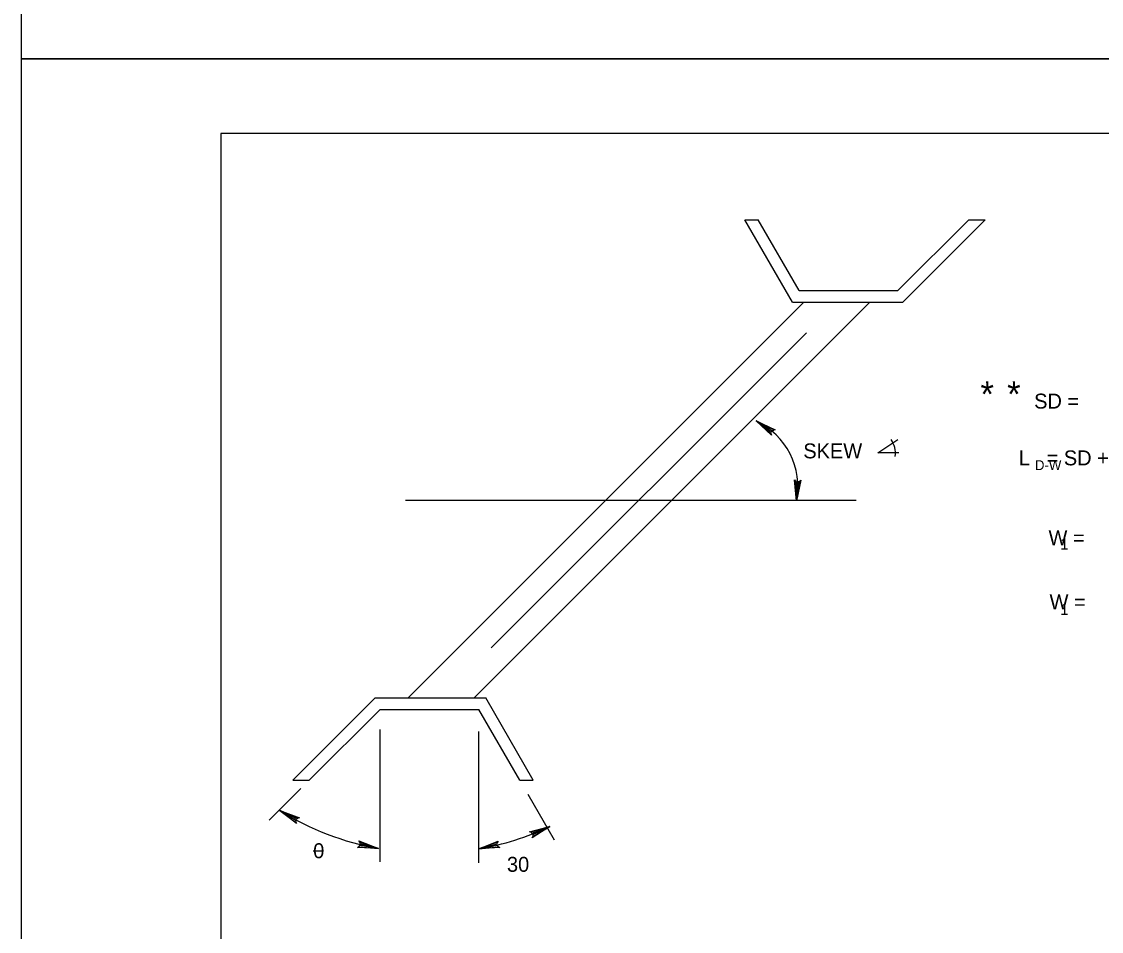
# Model space of a CAD drawing. Extents: x 638877 to 639960, y 297341 to 299123.
# Drawn here: x 638877.2 to 639093.9, y 297760.1 to 297942.8 of the extents above; entities that cross this region are included whole.
import ezdxf

# ---------------------------------------------------------------- set-up
doc = ezdxf.new("R2010")
doc.units = 0
for name, color, linetype in [('1', 7, 'Continuous'), ('3', 7, 'Continuous'), ('PLT-BNDY', 7, 'Continuous')]:
    doc.layers.add(name, color=color, linetype=linetype)

msp = doc.modelspace()

# ---------------------------------------------------------------- linework, layer by layer
at = {"layer": '1'}
for p, q in [((639703.19, 297920.28), (638917.19, 297920.28)), ((638917.19, 297920.28), (638917.19, 297356.28))]:
    msp.add_line(p, q, dxfattribs=at)
at = {"layer": '3'}
for p, q in [((639031.89, 297886.42), (639022.33, 297902.96)), ((639022.33, 297902.96), (639025.03, 297902.96)), ((639033.24, 297888.76), (639025.03, 297902.96)), ((639053.09, 297888.76), (639067.3, 297902.96)), ((639054.07, 297886.42), (639070.61, 297902.96)), ((639067.3, 297902.96), (639070.61, 297902.96)), ((639033.24, 297888.76), (639053.09, 297888.76)), ((638954.78, 297806.99), (639034.2, 297886.42)), ((638968.02, 297806.99), (639047.45, 297886.42)), ((639031.89, 297886.42), (639054.07, 297886.42)), ((638971.45, 297817.04), (639034.71, 297880.3)), ((639049.07, 297856.18), (639053.08, 297858.84)), ((639053.25, 297856.18), (639049.07, 297856.18)), ((638954.22, 297846.71), (639044.7, 297846.71)), ((638994.49, 297846.71), (638994.49, 297846.71)), ((639007.73, 297846.71), (639007.73, 297846.71)), ((638931.62, 297790.45), (638948.17, 297806.99)), ((638948.17, 297806.99), (638970.34, 297806.99)), ((638979.89, 297790.45), (638970.34, 297806.99)), ((638934.93, 297790.45), (638949.13, 297804.65)), ((638949.13, 297804.65), (638968.99, 297804.65)), ((638977.19, 297790.45), (638968.99, 297804.65)), ((638949.13, 297774.03), (638949.13, 297800.64)), ((638968.99, 297773.83), (638968.99, 297800.22)), ((638931.62, 297790.45), (638934.93, 297790.45)), ((638977.19, 297790.45), (638979.89, 297790.45)), ((638926.88, 297782.4), (638933.23, 297788.75)), ((638984.13, 297778.43), (638978.85, 297787.58)), ((638935.73, 297776.29), (638937.68, 297776.29))]:
    msp.add_line(p, q, dxfattribs=at)
for points in [[(639027.64, 297859.96), (639027.67, 297860.28), (639024.62, 297862.58), (639027.64, 297859.96), (639027.71, 297859.7), (639024.62, 297862.58), (639027.89, 297860.61), (639028.17, 297860.77), (639024.62, 297862.58), (639028.45, 297860.81), (639028.17, 297860.77)], [(639033.43, 297850.49), (639033.14, 297850.36), (639032.71, 297846.56), (639033.43, 297850.49), (639033.62, 297850.69), (639032.71, 297846.56), (639032.74, 297850.38), (639032.46, 297850.54), (639032.71, 297846.56), (639032.29, 297850.76), (639032.46, 297850.54)], [(638932.26, 297781.98), (638932.27, 297782.31), (638929.03, 297784.33), (638932.26, 297781.98), (638932.36, 297781.73), (638929.03, 297784.33), (638932.46, 297782.66), (638932.72, 297782.84), (638929.03, 297784.33), (638933, 297782.9), (638932.72, 297782.84)], [(638979.37, 297780.02), (638979.63, 297779.82), (638983.21, 297781.15), (638979.37, 297780.02), (638979.12, 297780.1), (638983.21, 297781.15), (638979.79, 297779.45), (638979.77, 297779.14), (638983.21, 297781.15), (638979.65, 297778.88), (638979.77, 297779.14)], [(638945.03, 297778.03), (638945.11, 297777.72), (638948.8, 297776.71), (638945.03, 297778.03), (638944.86, 297778.24), (638948.8, 297776.71), (638945.03, 297777.33), (638944.83, 297777.08), (638948.8, 297776.71), (638944.59, 297776.94), (638944.83, 297777.08)], [(638972.91, 297777.05), (638972.71, 297777.3), (638968.94, 297776.65), (638972.91, 297777.05), (638973.15, 297776.93), (638968.94, 297776.65), (638972.61, 297777.69), (638972.68, 297777.99), (638968.94, 297776.65), (638972.85, 297778.23), (638972.68, 297777.99)]]:
    msp.add_lwpolyline(points, dxfattribs=at)
for centre, radius, start, end in [((639018.55, 297849.47), 14.45, 348.463, 65.1663), ((639047.28, 297855.99), 5.3, 354.1715, 33.0785), ((638959.06, 297832.86), 57.07, 238.2426, 259.6427), ((638959.06, 297832.86), 57.07, 279.9638, 295.0339)]:
    msp.add_arc(centre, radius, start, end, dxfattribs=at)
at = {"layer": 'PLT-BNDY'}
for points in [[(638877.19, 298529.28), (639718.19, 298529.28), (639718.19, 297935.28), (638877.19, 297935.28)], [(638877.19, 297935.28), (639718.19, 297935.28), (639718.19, 297341.28), (638877.19, 297341.28)]]:
    msp.add_lwpolyline(points, close=True, dxfattribs=at)

# ---------------------------------------------------------------- texts
at = {"layer": '1'}
for s, height, p in [('*', 5.19, (639069.65, 297865.38)), ('*', 5.19, (639075.01, 297865.38)), ('D-W', 1.984, (639080.58, 297852.72))]:
    msp.add_text(s, height=height, dxfattribs=at).set_placement(p)
at = {"layer": '3'}
for s, height, p in [('SD =', 3, (639080.42, 297865.07)), ('SKEW', 3, (639034.09, 297855.07)), ("L   = SD + 2.3'", 3, (639077.35, 297853.67)), ('W =', 3, (639083.31, 297837.64)), ('1', 2.25, (639085.64, 297836.76)), ('W =', 3, (639083.52, 297824.74)), ('1', 2.25, (639085.65, 297823.62)), ('0', 3, (638935.72, 297774.78)), ('30', 3, (638974.61, 297772.05))]:
    msp.add_text(s, height=height, dxfattribs=at).set_placement(p)

doc.saveas('drawing.dxf')
